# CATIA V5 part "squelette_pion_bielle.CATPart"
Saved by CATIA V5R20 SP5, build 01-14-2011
Part number: squelette_pion_bielle
Publications: "hauteur", "diametre", "Plan.1", "Point.1", "Plan.2", "Point.2", "Droite.1"
Bounding box of the stored display mesh (mm): x 0 to 0, y 0 to 13.22, z 0 to 0
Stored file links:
  F:\iao\catia\projet iao\squelette_pion_bielle.CATPart
  F:\iao\catia\projet iao\fhartmann.CATProduct
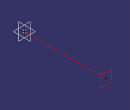
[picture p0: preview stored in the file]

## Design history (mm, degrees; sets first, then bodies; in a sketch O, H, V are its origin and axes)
Parameters
  hauteur = 13.22 mm {= External.bielle1_epaisseur *2}
  diametre = 10 mm {= External.bielle_diametre_int}
External parameters (linked from other documents)
  External.bielle1_epaisseur = 6.61 mm
  External.bielle_diametre_int = 10 mm
Set1
  Plane1: type Offset, RefPlane zx-plane, Offset 0
  Point1: type OnPlane, Support Plane1, H 0, V 0, Direction (-1, 0, 0)
  Plane2: type Offset, RefPlane Plane1, Offset 13.22 {= hauteur}
  Point2: type OnPlane, Support Plane2, H 0, V 0, Direction (-1, 0, 0)
  Line1: type PtPt, FirstPoint Point1, SecondPoint Point2
Body1 (main body)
